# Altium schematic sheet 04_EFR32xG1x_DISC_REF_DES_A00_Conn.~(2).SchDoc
size 420 x 297 mm
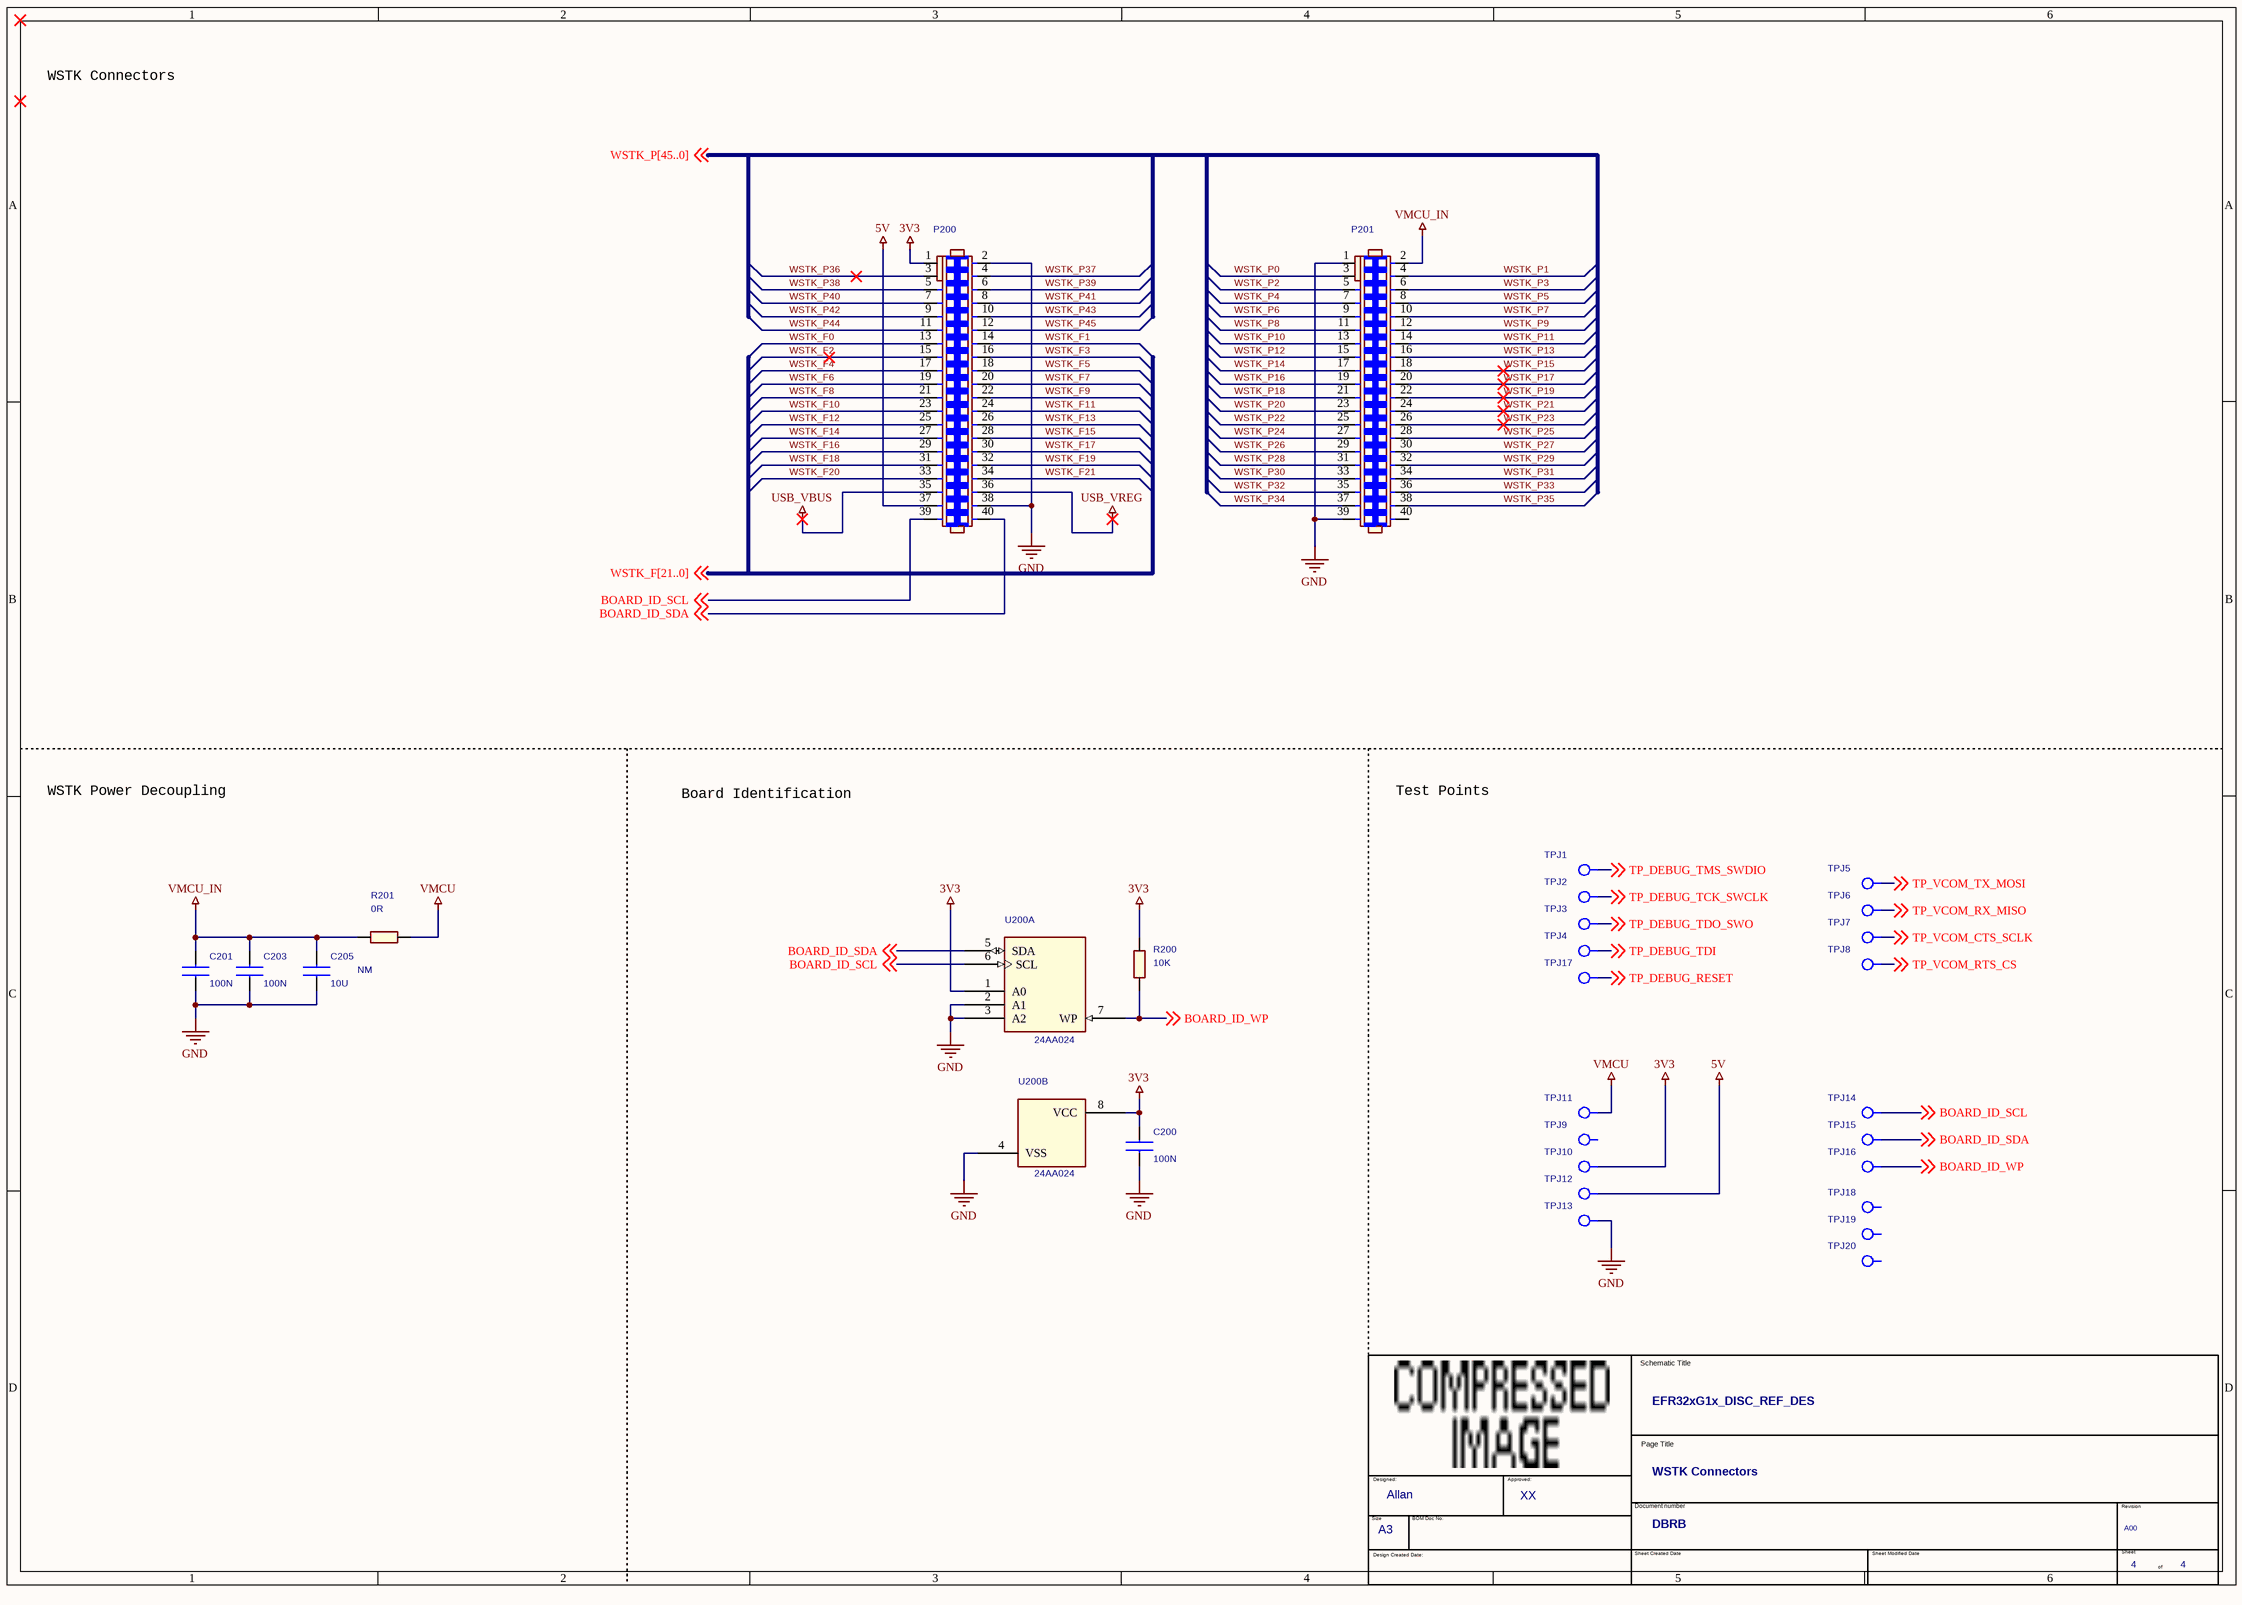
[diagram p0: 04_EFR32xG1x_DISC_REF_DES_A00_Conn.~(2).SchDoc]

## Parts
*  OrgAddr2: XX  OrgAddr1: Allan  Page Count: 4  Doc: DBRB  Title: EFR32xG1x_DISC_REF_DES  RevCode: A00  Page Size: A3  Page Title: WSTK Connectors  (hidden comment: TitleBlock_EnergyMicro_A3)  (graphical)
C200  100N  [C0402_L]
C201  100N  [C0402_L]
C203  100N  [C0402_L]
C205  10U  Not Mounted: NM  [C0805_L]
P200  SOCKET_2X20_1.27MM_SMD  [SAM_SFC-120-T2-D-A-2X20_SNUM]  (value not drawn)
P201  SOCKET_2X20_1.27MM_SMD  [SAM_SFC-120-T2-D-A-2X20_SNUM]  (value not drawn)
R200  10K  [R0402_L]
R201  0R  [R0402_L]
TPJ1  TPJ_SMD  [TP_1.0_SMD]  (value not drawn)
TPJ2  TPJ_SMD  [TP_1.0_SMD]  (value not drawn)
TPJ3  TPJ_SMD  [TP_1.0_SMD]  (value not drawn)
TPJ4  TPJ_SMD  [TP_1.0_SMD]  (value not drawn)
TPJ5  TPJ_SMD  [TP_1.0_SMD]  (value not drawn)
TPJ6  TPJ_SMD  [TP_1.0_SMD]  (value not drawn)
TPJ7  TPJ_SMD  [TP_1.0_SMD]  (value not drawn)
TPJ8  TPJ_SMD  [TP_1.0_SMD]  (value not drawn)
TPJ9  TPJ_SMD  [TP_1.0_SMD]  (value not drawn)
TPJ10  TPJ_SMD  [TP_1.0_SMD]  (value not drawn)
TPJ11  TPJ_SMD  [TP_1.0_SMD]  (value not drawn)
TPJ12  TPJ_SMD  [TP_1.0_SMD]  (value not drawn)
TPJ13  TPJ_SMD  [TP_1.0_SMD]  (value not drawn)
TPJ14  TPJ_SMD  [TP_1.0_SMD]  (value not drawn)
TPJ15  TPJ_SMD  [TP_1.0_SMD]  (value not drawn)
TPJ16  TPJ_SMD  [TP_1.0_SMD]  (value not drawn)
TPJ17  TPJ_SMD  [TP_1.0_SMD]  (value not drawn)
TPJ18  TPJ_SMD  [TP_1.0_SMD]  (value not drawn)
TPJ19  TPJ_SMD  [TP_1.0_SMD]  (value not drawn)
TPJ20  TPJ_SMD  [TP_1.0_SMD]  (value not drawn)
U200  24AA024  [TDFN8_M050_2.0X3.0_EP]  (parts A,B of 2)

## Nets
3V3: C200.1 P200.1 R200.2 TPJ10.1(TP) U200.1(A0) U200.8(VCC)
5V: P200.37 TPJ12.1(TP)
GND: C200.2 C201.2 C203.2 C205.2 P200.2 P200.38 P201.1 P201.39 TPJ13.1(TP) U200.2(A1) U200.3(A2) U200.4(VSS)
USB_VBUS: P200.35
USB_VREG: P200.36
VMCU: R201.2 TPJ11.1(TP)
VMCU_IN: C201.1 C203.1 C205.1 P201.2 R201.1
BOARD_ID_SCL: P200.39 TPJ14.1(TP) U200.6(SCL) ; off-sheet BOARD_ID_SCL
BOARD_ID_SDA: P200.40 TPJ15.1(TP) U200.5(SDA) ; off-sheet BOARD_ID_SDA
BOARD_ID_WP: R200.1 TPJ16.1(TP) U200.7(WP) ; off-sheet BOARD_ID_WP
TP_DEBUG_RESET: TPJ17.1(TP) ; off-sheet TP_DEBUG_RESET
TP_DEBUG_TCK_SWCLK: TPJ2.1(TP) ; off-sheet TP_DEBUG_TCK_SWCLK
TP_DEBUG_TDI: TPJ4.1(TP) ; off-sheet TP_DEBUG_TDI
TP_DEBUG_TDO_SWO: TPJ3.1(TP) ; off-sheet TP_DEBUG_TDO_SWO
TP_DEBUG_TMS_SWDIO: TPJ1.1(TP) ; off-sheet TP_DEBUG_TMS_SWDIO
TP_VCOM_CTS_SCLK: TPJ7.1(TP) ; off-sheet TP_VCOM_CTS_SCLK
TP_VCOM_RTS_CS: TPJ8.1(TP) ; off-sheet TP_VCOM_RTS_CS
TP_VCOM_RX_MISO: TPJ6.1(TP) ; off-sheet TP_VCOM_RX_MISO
TP_VCOM_TX_MOSI: TPJ5.1(TP) ; off-sheet TP_VCOM_TX_MOSI
WSTK_F0: P200.13
WSTK_F1: P200.14
WSTK_F2: P200.15
WSTK_F3: P200.16
WSTK_F4: P200.17
WSTK_F5: P200.18
WSTK_F6: P200.19
WSTK_F7: P200.20
WSTK_F8: P200.21
WSTK_F9: P200.22
WSTK_F10: P200.23
WSTK_F11: P200.24
WSTK_F12: P200.25
WSTK_F13: P200.26
WSTK_F14: P200.27
WSTK_F15: P200.28
WSTK_F16: P200.29
WSTK_F17: P200.30
WSTK_F18: P200.31
WSTK_F19: P200.32
WSTK_F20: P200.33
WSTK_F21: P200.34
WSTK_P0: P201.3
WSTK_P1: P201.4
WSTK_P2: P201.5
WSTK_P3: P201.6
WSTK_P4: P201.7
WSTK_P5: P201.8
WSTK_P6: P201.9
WSTK_P7: P201.10
WSTK_P8: P201.11
WSTK_P9: P201.12
WSTK_P10: P201.13
WSTK_P11: P201.14
WSTK_P12: P201.15
WSTK_P13: P201.16
WSTK_P14: P201.17
WSTK_P15: P201.18
WSTK_P16: P201.19
WSTK_P17: P201.20
WSTK_P18: P201.21
WSTK_P19: P201.22
WSTK_P20: P201.23
WSTK_P21: P201.24
WSTK_P22: P201.25
WSTK_P23: P201.26
WSTK_P24: P201.27
WSTK_P25: P201.28
WSTK_P26: P201.29
WSTK_P27: P201.30
WSTK_P28: P201.31
WSTK_P29: P201.32
WSTK_P30: P201.33
WSTK_P31: P201.34
WSTK_P32: P201.35
WSTK_P33: P201.36
WSTK_P34: P201.37
WSTK_P35: P201.38
WSTK_P36: P200.3
WSTK_P37: P200.4
WSTK_P38: P200.5
WSTK_P39: P200.6
WSTK_P40: P200.7
WSTK_P41: P200.8
WSTK_P42: P200.9
WSTK_P43: P200.10
WSTK_P44: P200.11
WSTK_P45: P200.12

Not connected (* = marked no-connect by the designer): P201 40; TPJ9 1(TP); TPJ18 1(TP); TPJ19 1(TP); TPJ20 1(TP)

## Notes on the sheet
- WSTK Connectors
- WSTK Power Decoupling
- Board Identification
- Test Points

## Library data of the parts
C200 C201 C203 = C0402: Rating: 16V; Tolerance: 10%
C205 = C0805: Rating: 10V; Tolerance: 10%
P200 P201 = SOCKET_2X20_1.27MM_SMD: Mfg: Samtec; Mfg #: SFC-120-T2-L-D-A-K-TR
R200 R201 = R0402
U200 = 24AA024: Mfg #: 24AA024T-I/MNY; Mfg: Microchip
